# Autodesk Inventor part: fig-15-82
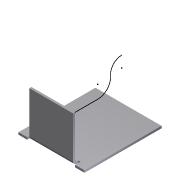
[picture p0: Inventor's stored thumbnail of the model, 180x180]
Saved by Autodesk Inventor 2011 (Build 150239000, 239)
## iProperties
Shininess: 77.0
Angle Display Precision: 2
Document Length Units: 11269
Document Angle Units: 11279
Document Time Units: 11290
Document Mass Units: 11283
Document Length Units Precision: 3
Document Angle Units Precision: 2
Compacted: True
Created: 2002-04
Part Number: fig-15-82
Document SubType Name: Sheet Metal
Density: 1 g/cm^3
Sheet Metal Rule: Default
Density: 0.0
Volumn: 0.0
Area: 0.0
PropertySet Name: Model Information
Control State: 0
Master: False
Checked Out: False
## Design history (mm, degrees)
node "Face1"
  sketch "Sketch1"
    geometry: L1 (-24.824, 17.882)-(5.529, 17.882); L2 (5.529, 17.882)-(5.529, -17.529); L3 (5.529, -17.529)-(-24.824, -17.529); L4 (-24.824, -17.529)-(-24.824, 17.882)
    constraints: 8 end point, 2 parallel, 1 horizontal, 1 perpendicular
node "Flange1"
sketch "Sketch5"
  geometry: L1 (0, 1)-(0, 11.431); A1 r 5.855 centre (-5.855, 11.431) between (0, 11.431) and (-6.422, 17.259); A2 r 5.142 centre (-6.92, 22.376) between (-12.062, 22.382) and (-6.422, 17.259)
  constraints: 4 point on circle, 2 centre point, 2 end point, 2 tangent
body "Solid1"
face "Plate1" dims "Thickness" = 1
sketch "Sketch3"
  geometry: L1 (25.353, 0)-(5.353, 0); L2 (5.353, 0)-(5.353, 20); L3 (5.353, 20)-(25.353, 20); L4 (25.353, 20)-(25.353, 0)
  constraints: 8 end point
face "Plate3" dims "d5" = 20, "d6" = 90 deg, "d7" = 1 (= BendRadius), "d11" = 5, "d12" = 20, "Thickness" = 1, "MinimumRemnant" = 2 (= 2 x Thickness), "BendReliefWidth" = 1 (= Thickness)
bend "Bend2" dims "d5" = 20, "d6" = 90 deg, "d7" = 1 (= BendRadius), "d21" = 1 (= BendReliefWidth), "d22" = 0.5 (= BendReliefDepth), "d23" = 2 (= MinimumRemnant), "SeamGap" = 0.01, "Thickness" = 1, "MinimumRemnant" = 2 (= 2 x Thickness), "BendReliefWidth" = 1 (= Thickness), "TransitionRadius" = 1 (= BendRadius)
other parameters: "BendRadius" = 1 (= Thickness), "BendReliefDepth" = 0.5 (= 0.5 x Thickness), "CornerReliefSize" = 4 (= 4 x Thickness), "d0" = 1 (= BendRadius), "d4" = 1 (= BendRadius), "JacobiRadiusSize" = 1 (= Thickness), "GapSize" = 1 (= Thickness)
